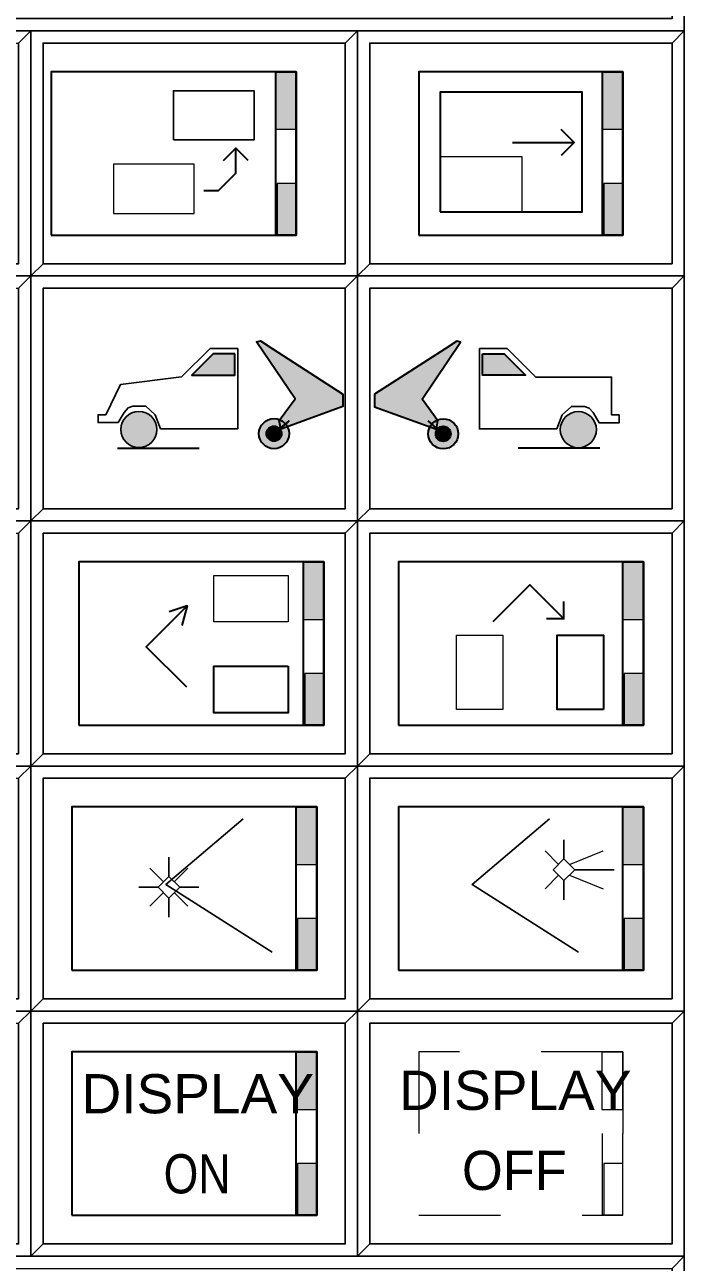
# Model space of a CAD drawing. Extents: x 95906.8 to 95923.6, y 90964.8 to 90972.8.
# Drawn here: x 95917.125 to 95917.932, y 90966.454 to 90967.969 of the extents above; entities that cross this region are included whole.
import ezdxf
from ezdxf.enums import TextEntityAlignment as Align

# ---------------------------------------------------------------- set-up
doc = ezdxf.new("R2010")
doc.units = 0
doc.header["$LTSCALE"] = 0.019
doc.linetypes.add('MEDIUM_DASHED', pattern=[4.5, 3, -1.5])
for name, color, linetype, lineweight in [('11', 7, 'Continuous', 25), ('2', 7, 'Continuous', 13), ('3', 7, 'Continuous', 25), ('6', 7, 'Continuous', 25)]:
    doc.layers.add(name, color=color, linetype=linetype, lineweight=lineweight)

msp = doc.modelspace()

# ---------------------------------------------------------------- hatches: boundary and pattern name
at = {"layer": '6'}
for points in [[(95917.4573, 90967.9117), (95917.4315, 90967.9117), (95917.4315, 90967.8412), (95917.4573, 90967.8412)], [(95917.8573, 90967.9117), (95917.8315, 90967.9117), (95917.8315, 90967.8412), (95917.8573, 90967.8412)], [(95917.4339, 90967.7117), (95917.4573, 90967.7117), (95917.4573, 90967.775), (95917.4339, 90967.775)], [(95917.8339, 90967.7117), (95917.8573, 90967.7117), (95917.8573, 90967.775), (95917.8339, 90967.775)], [(95917.4486, 90967.4845), (95917.4382, 90967.4746), (95917.4365, 90967.4846), (95917.456, 90967.5112), (95917.4087, 90967.5809), (95917.4134, 90967.5821), (95917.4276, 90967.5727), (95917.5143, 90967.5171), (95917.5143, 90967.5017), (95917.4394, 90967.4745), (95917.4382, 90967.4757)], [(95917.6186, 90967.4843), (95917.629, 90967.4744), (95917.6307, 90967.4844), (95917.6112, 90967.511), (95917.6585, 90967.5807), (95917.6538, 90967.5819), (95917.6396, 90967.5725), (95917.5529, 90967.5169), (95917.5529, 90967.5015), (95917.6278, 90967.4743), (95917.629, 90967.4755)], [(95917.3819, 90967.5664), (95917.3554, 90967.5664), (95917.3294, 90967.5404), (95917.3819, 90967.5404)], [(95917.6853, 90967.5662), (95917.7118, 90967.5662), (95917.7378, 90967.5402), (95917.6853, 90967.5402)], [(95917.2426, 90967.4737, 1), (95917.2867, 90967.4737, 1)], [(95917.8246, 90967.4735, 1), (95917.7805, 90967.4735, 1)], [(95917.4484, 90967.4686, 1), (95917.4116, 90967.4686, 1)], [(95917.6188, 90967.4684, 1), (95917.6556, 90967.4684, 1)], [(95917.4392, 90967.4686, 1), (95917.4208, 90967.4686, 1)], [(95917.628, 90967.4684, 1), (95917.6464, 90967.4684, 1)], [(95917.4912, 90967.3117), (95917.4654, 90967.3117), (95917.4654, 90967.2412), (95917.4912, 90967.2412)], [(95917.8823, 90967.3117), (95917.8565, 90967.3117), (95917.8565, 90967.2412), (95917.8823, 90967.2412)], [(95917.4678, 90967.1117), (95917.4912, 90967.1117), (95917.4912, 90967.175), (95917.4678, 90967.175)], [(95917.8589, 90967.1117), (95917.8823, 90967.1117), (95917.8823, 90967.175), (95917.8589, 90967.175)], [(95917.4823, 90967.0117), (95917.4565, 90967.0117), (95917.4565, 90966.9412), (95917.4823, 90966.9412)], [(95917.8823, 90967.0117), (95917.8565, 90967.0117), (95917.8565, 90966.9412), (95917.8823, 90966.9412)], [(95917.4589, 90966.8117), (95917.4823, 90966.8117), (95917.4823, 90966.875), (95917.4589, 90966.875)], [(95917.8589, 90966.8117), (95917.8823, 90966.8117), (95917.8823, 90966.875), (95917.8589, 90966.875)], [(95917.4823, 90966.7117), (95917.4565, 90966.7117), (95917.4565, 90966.6412), (95917.4823, 90966.6412)], [(95917.4589, 90966.5117), (95917.4823, 90966.5117), (95917.4823, 90966.575), (95917.4589, 90966.575)]]:
    msp.add_hatch(color=256, dxfattribs=at).paths.add_polyline_path(points)

# ---------------------------------------------------------------- linework, layer by layer
at = {"layer": '11'}
for points in [[(95917.1473, 90967.6767), (95917.5173, 90967.6767), (95917.5173, 90967.9467), (95917.1473, 90967.9467)], [(95917.5473, 90967.6767), (95917.9173, 90967.6767), (95917.9173, 90967.9467), (95917.5473, 90967.9467)], [(95917.1473, 90967.3767), (95917.5173, 90967.3767), (95917.5173, 90967.6467), (95917.1473, 90967.6467)], [(95917.5473, 90967.3767), (95917.9173, 90967.3767), (95917.9173, 90967.6467), (95917.5473, 90967.6467)], [(95917.1473, 90967.0767), (95917.5173, 90967.0767), (95917.5173, 90967.3467), (95917.1473, 90967.3467)], [(95917.5473, 90967.0767), (95917.9173, 90967.0767), (95917.9173, 90967.3467), (95917.5473, 90967.3467)], [(95917.1473, 90966.7767), (95917.5173, 90966.7767), (95917.5173, 90967.0467), (95917.1473, 90967.0467)], [(95917.5473, 90966.7767), (95917.9173, 90966.7767), (95917.9173, 90967.0467), (95917.5473, 90967.0467)], [(95917.1473, 90966.4767), (95917.5173, 90966.4767), (95917.5173, 90966.7467), (95917.1473, 90966.7467)], [(95917.5473, 90966.4767), (95917.9173, 90966.4767), (95917.9173, 90966.7467), (95917.5473, 90966.7467)]]:
    msp.add_lwpolyline(points, close=True, dxfattribs=at)
at = {"layer": '2'}
for points in [[(95916.7323, 90967.9617), (95916.7323, 90967.6617), (95916.7473, 90967.6767), (95916.7473, 90967.9467), (95917.1173, 90967.9467), (95917.1323, 90967.9617)], [(95917.1323, 90967.9617), (95917.1323, 90967.6617), (95917.1473, 90967.6767), (95917.1473, 90967.9467), (95917.5173, 90967.9467), (95917.5323, 90967.9617)], [(95917.5323, 90967.9617), (95917.5323, 90967.6617), (95917.5473, 90967.6767), (95917.5473, 90967.9467), (95917.9173, 90967.9467), (95917.9323, 90967.9617)], [(95916.7323, 90967.6617), (95916.7323, 90967.3617), (95916.7473, 90967.3767), (95916.7473, 90967.6467), (95917.1173, 90967.6467), (95917.1323, 90967.6617)], [(95917.1323, 90967.6617), (95917.1323, 90967.3617), (95917.1473, 90967.3767), (95917.1473, 90967.6467), (95917.5173, 90967.6467), (95917.5323, 90967.6617)], [(95917.5323, 90967.6617), (95917.5323, 90967.3617), (95917.5473, 90967.3767), (95917.5473, 90967.6467), (95917.9173, 90967.6467), (95917.9323, 90967.6617)], [(95916.7323, 90967.3617), (95916.7323, 90967.0617), (95916.7473, 90967.0767), (95916.7473, 90967.3467), (95917.1173, 90967.3467), (95917.1323, 90967.3617)], [(95917.1323, 90967.3617), (95917.1323, 90967.0617), (95917.1473, 90967.0767), (95917.1473, 90967.3467), (95917.5173, 90967.3467), (95917.5323, 90967.3617)], [(95917.5323, 90967.3617), (95917.5323, 90967.0617), (95917.5473, 90967.0767), (95917.5473, 90967.3467), (95917.9173, 90967.3467), (95917.9323, 90967.3617)], [(95916.7323, 90967.0617), (95916.7323, 90966.7617), (95916.7473, 90966.7767), (95916.7473, 90967.0467), (95917.1173, 90967.0467), (95917.1323, 90967.0617)], [(95917.1323, 90967.0617), (95917.1323, 90966.7617), (95917.1473, 90966.7767), (95917.1473, 90967.0467), (95917.5173, 90967.0467), (95917.5323, 90967.0617)], [(95917.5323, 90967.0617), (95917.5323, 90966.7617), (95917.5473, 90966.7767), (95917.5473, 90967.0467), (95917.9173, 90967.0467), (95917.9323, 90967.0617)], [(95916.7323, 90966.7617), (95916.7323, 90966.4617), (95916.7473, 90966.4767), (95916.7473, 90966.7467), (95917.1173, 90966.7467), (95917.1323, 90966.7617)], [(95917.1323, 90966.7617), (95917.1323, 90966.4617), (95917.1473, 90966.4767), (95917.1473, 90966.7467), (95917.5173, 90966.7467), (95917.5323, 90966.7617)], [(95917.5323, 90966.7617), (95917.5323, 90966.4617), (95917.5473, 90966.4767), (95917.5473, 90966.7467), (95917.9173, 90966.7467), (95917.9323, 90966.7617)], [(95916.3323, 90966.4617), (95916.3323, 90966.3617), (95916.3473, 90966.3767), (95916.3473, 90966.4467), (95917.9173, 90966.4467), (95917.9323, 90966.4617)]]:
    msp.add_lwpolyline(points, close=True, dxfattribs=at)
at = {"layer": '3'}
for points in [[(95916.3323, 90967.9617), (95917.9323, 90967.9617), (95917.9323, 90968.0617), (95917.9173, 90968.0467), (95917.9173, 90967.9767), (95916.3473, 90967.9767)], [(95916.7323, 90967.6617), (95917.1323, 90967.6617), (95917.1323, 90967.9617), (95917.1173, 90967.9467), (95917.1173, 90967.6767), (95916.7473, 90967.6767)], [(95917.1323, 90967.6617), (95917.5323, 90967.6617), (95917.5323, 90967.9617), (95917.5173, 90967.9467), (95917.5173, 90967.6767), (95917.1473, 90967.6767)], [(95917.5323, 90967.6617), (95917.9323, 90967.6617), (95917.9323, 90967.9617), (95917.9173, 90967.9467), (95917.9173, 90967.6767), (95917.5473, 90967.6767)], [(95916.7323, 90967.3617), (95917.1323, 90967.3617), (95917.1323, 90967.6617), (95917.1173, 90967.6467), (95917.1173, 90967.3767), (95916.7473, 90967.3767)], [(95917.1323, 90967.3617), (95917.5323, 90967.3617), (95917.5323, 90967.6617), (95917.5173, 90967.6467), (95917.5173, 90967.3767), (95917.1473, 90967.3767)], [(95917.5323, 90967.3617), (95917.9323, 90967.3617), (95917.9323, 90967.6617), (95917.9173, 90967.6467), (95917.9173, 90967.3767), (95917.5473, 90967.3767)], [(95916.7323, 90967.0617), (95917.1323, 90967.0617), (95917.1323, 90967.3617), (95917.1173, 90967.3467), (95917.1173, 90967.0767), (95916.7473, 90967.0767)], [(95917.1323, 90967.0617), (95917.5323, 90967.0617), (95917.5323, 90967.3617), (95917.5173, 90967.3467), (95917.5173, 90967.0767), (95917.1473, 90967.0767)], [(95917.5323, 90967.0617), (95917.9323, 90967.0617), (95917.9323, 90967.3617), (95917.9173, 90967.3467), (95917.9173, 90967.0767), (95917.5473, 90967.0767)], [(95916.7323, 90966.7617), (95917.1323, 90966.7617), (95917.1323, 90967.0617), (95917.1173, 90967.0467), (95917.1173, 90966.7767), (95916.7473, 90966.7767)], [(95917.1323, 90966.7617), (95917.5323, 90966.7617), (95917.5323, 90967.0617), (95917.5173, 90967.0467), (95917.5173, 90966.7767), (95917.1473, 90966.7767)], [(95917.5323, 90966.7617), (95917.9323, 90966.7617), (95917.9323, 90967.0617), (95917.9173, 90967.0467), (95917.9173, 90966.7767), (95917.5473, 90966.7767)], [(95916.7323, 90966.4617), (95917.1323, 90966.4617), (95917.1323, 90966.7617), (95917.1173, 90966.7467), (95917.1173, 90966.4767), (95916.7473, 90966.4767)], [(95917.1323, 90966.4617), (95917.5323, 90966.4617), (95917.5323, 90966.7617), (95917.5173, 90966.7467), (95917.5173, 90966.4767), (95917.1473, 90966.4767)], [(95917.5323, 90966.4617), (95917.9323, 90966.4617), (95917.9323, 90966.7617), (95917.9173, 90966.7467), (95917.9173, 90966.4767), (95917.5473, 90966.4767)], [(95916.3323, 90966.3617), (95917.9323, 90966.3617), (95917.9323, 90966.4617), (95917.9173, 90966.4467), (95917.9173, 90966.3767), (95916.3473, 90966.3767)]]:
    msp.add_lwpolyline(points, close=True, dxfattribs=at)
at = {"layer": '6', "lineweight": 35}
for p, q in [((95917.7977, 90967.8252), (95917.7817, 90967.8411)), ((95917.3832, 90967.8181), (95917.3678, 90967.8027)), ((95917.3237, 90967.258), (95917.3018, 90967.2503)), ((95917.7847, 90967.242), (95917.7635, 90967.242))]:
    msp.add_line(p, q, dxfattribs=at)
at = {"layer": '6', "linetype": 'MEDIUM_DASHED', "lineweight": 35}
for p, q in [((95917.2382, 90967.451), (95917.3876, 90967.451)), ((95917.829, 90967.4508), (95917.6796, 90967.4508))]:
    msp.add_line(p, q, dxfattribs=at)
at = {"layer": '6'}
for p, q in [((95917.785, 90966.9479), (95917.785, 90966.9713)), ((95917.785, 90966.9479), (95917.785, 90966.9713)), ((95917.3013, 90966.9266), (95917.3013, 90966.95)), ((95917.3013, 90966.9266), (95917.3013, 90966.95)), ((95917.7982, 90966.9346), (95917.8466, 90966.9346)), ((95917.7982, 90966.9346), (95917.8466, 90966.9346)), ((95917.785, 90966.9214), (95917.785, 90966.898)), ((95917.785, 90966.9214), (95917.785, 90966.898)), ((95917.2881, 90966.9133), (95917.2646, 90966.9133)), ((95917.3145, 90966.9133), (95917.3379, 90966.9133)), ((95917.3145, 90966.9133), (95917.3379, 90966.9133)), ((95917.3013, 90966.9001), (95917.3013, 90966.8767)), ((95917.3013, 90966.9001), (95917.3013, 90966.8767)), ((95917.5173, 90966.7147), (95917.5173, 90966.503)), ((95917.5173, 90966.7147), (95917.5173, 90966.503)), ((95917.5173, 90966.7147), (95917.5173, 90966.503)), ((95917.9173, 90966.7147), (95917.9173, 90966.503))]:
    msp.add_line(p, q, dxfattribs=at)
at = {"layer": '6', "linetype": 'MEDIUM_DASHED', "lineweight": 13}
for p, q in [((95917.7784, 90966.9412), (95917.7618, 90966.9578)), ((95917.7784, 90966.9412), (95917.7618, 90966.9578)), ((95917.7916, 90966.9412), (95917.8332, 90966.9578)), ((95917.7916, 90966.9412), (95917.8332, 90966.9578)), ((95917.2947, 90966.9199), (95917.2781, 90966.9365)), ((95917.2947, 90966.9199), (95917.2781, 90966.9365)), ((95917.3079, 90966.9199), (95917.3245, 90966.9365)), ((95917.3079, 90966.9199), (95917.3245, 90966.9365)), ((95917.7784, 90966.928), (95917.7618, 90966.9115)), ((95917.7784, 90966.928), (95917.7618, 90966.9115)), ((95917.7916, 90966.928), (95917.8332, 90966.9115)), ((95917.7916, 90966.928), (95917.8332, 90966.9115)), ((95917.2947, 90966.9067), (95917.2781, 90966.8902)), ((95917.2947, 90966.9067), (95917.2781, 90966.8902)), ((95917.3079, 90966.9067), (95917.3245, 90966.8902)), ((95917.3079, 90966.9067), (95917.3245, 90966.8902))]:
    msp.add_line(p, q, dxfattribs=at)
at = {"layer": '6', "lineweight": 13}
for p, q in [((95917.5173, 90966.503), (95917.5173, 90966.7147)), ((95917.5173, 90966.503), (95917.5173, 90966.7147)), ((95917.5173, 90966.503), (95917.5173, 90966.7147)), ((95917.9173, 90966.503), (95917.9173, 90966.7147))]:
    msp.add_line(p, q, dxfattribs=at)
at = {"layer": '6', "lineweight": 35}
for points in [[(95917.1573, 90967.7117), (95917.4573, 90967.7117), (95917.4573, 90967.9117), (95917.1573, 90967.9117)], [(95917.4573, 90967.7117), (95917.4323, 90967.7117), (95917.4323, 90967.9117), (95917.4573, 90967.9117)], [(95917.6073, 90967.7117), (95917.8573, 90967.7117), (95917.8573, 90967.9117), (95917.6073, 90967.9117)], [(95917.8573, 90967.7117), (95917.8323, 90967.7117), (95917.8323, 90967.9117), (95917.8573, 90967.9117)], [(95917.6334, 90967.7401), (95917.8072, 90967.7401), (95917.8072, 90967.8867), (95917.6334, 90967.8867)], [(95917.4486, 90967.4845), (95917.4382, 90967.4746), (95917.4365, 90967.4846), (95917.456, 90967.5112), (95917.4087, 90967.5809), (95917.4134, 90967.5821), (95917.4276, 90967.5727), (95917.5143, 90967.5171), (95917.5143, 90967.5017), (95917.4394, 90967.4745), (95917.4382, 90967.4757)], [(95917.6186, 90967.4843), (95917.629, 90967.4744), (95917.6307, 90967.4844), (95917.6112, 90967.511), (95917.6585, 90967.5807), (95917.6538, 90967.5819), (95917.6396, 90967.5725), (95917.5529, 90967.5169), (95917.5529, 90967.5015), (95917.6278, 90967.4743), (95917.629, 90967.4755)], [(95917.3819, 90967.5664), (95917.3554, 90967.5664), (95917.3294, 90967.5404), (95917.3819, 90967.5404)], [(95917.6853, 90967.5662), (95917.7118, 90967.5662), (95917.7378, 90967.5402), (95917.6853, 90967.5402)], [(95917.1912, 90967.1117), (95917.4912, 90967.1117), (95917.4912, 90967.3117), (95917.1912, 90967.3117)], [(95917.4912, 90967.1117), (95917.4662, 90967.1117), (95917.4662, 90967.3117), (95917.4912, 90967.3117)], [(95917.5823, 90967.1117), (95917.8823, 90967.1117), (95917.8823, 90967.3117), (95917.5823, 90967.3117)], [(95917.8823, 90967.1117), (95917.8573, 90967.1117), (95917.8573, 90967.3117), (95917.8823, 90967.3117)], [(95917.8333, 90967.1309), (95917.7765, 90967.1309), (95917.7765, 90967.2219), (95917.8333, 90967.2219)], [(95917.4472, 90967.1838), (95917.4472, 90967.127), (95917.3562, 90967.127), (95917.3562, 90967.1838)], [(95917.1823, 90966.8117), (95917.4823, 90966.8117), (95917.4823, 90967.0117), (95917.1823, 90967.0117)], [(95917.4823, 90966.8117), (95917.4573, 90966.8117), (95917.4573, 90967.0117), (95917.4823, 90967.0117)], [(95917.5823, 90966.8117), (95917.8823, 90966.8117), (95917.8823, 90967.0117), (95917.5823, 90967.0117)], [(95917.8823, 90966.8117), (95917.8573, 90966.8117), (95917.8573, 90967.0117), (95917.8823, 90967.0117)], [(95917.1823, 90966.5117), (95917.4823, 90966.5117), (95917.4823, 90966.7117), (95917.1823, 90966.7117)], [(95917.4823, 90966.5117), (95917.4573, 90966.5117), (95917.4573, 90966.7117), (95917.4823, 90966.7117)]]:
    msp.add_lwpolyline(points, close=True, dxfattribs=at)
at = {"layer": '6', "lineweight": 13}
for points in [[(95917.4573, 90967.9117), (95917.4315, 90967.9117), (95917.4315, 90967.8412), (95917.4573, 90967.8412)], [(95917.8573, 90967.9117), (95917.8315, 90967.9117), (95917.8315, 90967.8412), (95917.8573, 90967.8412)], [(95917.4339, 90967.7117), (95917.4573, 90967.7117), (95917.4573, 90967.775), (95917.4339, 90967.775)], [(95917.8339, 90967.7117), (95917.8573, 90967.7117), (95917.8573, 90967.775), (95917.8339, 90967.775)], [(95917.4912, 90967.3117), (95917.4654, 90967.3117), (95917.4654, 90967.2412), (95917.4912, 90967.2412)], [(95917.8823, 90967.3117), (95917.8565, 90967.3117), (95917.8565, 90967.2412), (95917.8823, 90967.2412)], [(95917.4678, 90967.1117), (95917.4912, 90967.1117), (95917.4912, 90967.175), (95917.4678, 90967.175)], [(95917.8589, 90967.1117), (95917.8823, 90967.1117), (95917.8823, 90967.175), (95917.8589, 90967.175)], [(95917.4823, 90967.0117), (95917.4565, 90967.0117), (95917.4565, 90966.9412), (95917.4823, 90966.9412)], [(95917.8823, 90967.0117), (95917.8565, 90967.0117), (95917.8565, 90966.9412), (95917.8823, 90966.9412)], [(95917.785, 90966.9214), (95917.7983, 90966.9347), (95917.785, 90966.9479), (95917.7717, 90966.9347)], [(95917.785, 90966.9214), (95917.7983, 90966.9347), (95917.785, 90966.9479), (95917.7717, 90966.9347)], [(95917.3013, 90966.9001), (95917.3146, 90966.9134), (95917.3013, 90966.9266), (95917.288, 90966.9134)], [(95917.3013, 90966.9001), (95917.3146, 90966.9134), (95917.3013, 90966.9266), (95917.288, 90966.9134)], [(95917.4589, 90966.8117), (95917.4823, 90966.8117), (95917.4823, 90966.875), (95917.4589, 90966.875)], [(95917.8589, 90966.8117), (95917.8823, 90966.8117), (95917.8823, 90966.875), (95917.8589, 90966.875)], [(95917.4823, 90966.7117), (95917.4565, 90966.7117), (95917.4565, 90966.6412), (95917.4823, 90966.6412)], [(95917.4589, 90966.5117), (95917.4823, 90966.5117), (95917.4823, 90966.575), (95917.4589, 90966.575)]]:
    msp.add_lwpolyline(points, close=True, dxfattribs=at)
at = {"layer": '6'}
for points in [[(95917.3068, 90967.8282), (95917.4055, 90967.8282), (95917.4055, 90967.8885), (95917.3068, 90967.8885)], [(95917.3857, 90967.573), (95917.3517, 90967.573), (95917.3166, 90967.538), (95917.242, 90967.5287), (95917.2239, 90967.4917), (95917.2145, 90967.4917), (95917.2145, 90967.4822), (95917.2391, 90967.4822), (95917.2466, 90967.4945), (95917.2514, 90967.5002), (95917.257, 90967.5021), (95917.2731, 90967.5021), (95917.2845, 90967.4917), (95917.2911, 90967.4746), (95917.3857, 90967.4746)], [(95917.6815, 90967.5728), (95917.7155, 90967.5728), (95917.7506, 90967.5378), (95917.8433, 90967.5379), (95917.8433, 90967.4915), (95917.8527, 90967.4915), (95917.8527, 90967.482), (95917.8281, 90967.482), (95917.8206, 90967.4943), (95917.8158, 90967.5), (95917.8102, 90967.5019), (95917.7941, 90967.5019), (95917.7827, 90967.4915), (95917.7761, 90967.4744), (95917.6815, 90967.4744)]]:
    msp.add_lwpolyline(points, close=True, dxfattribs=at)
at = {"layer": '6', "lineweight": 35}
for points in [[(95917.3442, 90967.7661), (95917.3619, 90967.7661), (95917.3832, 90967.7874), (95917.3832, 90967.8181), (95917.398, 90967.8033)], [(95917.7221, 90967.8252), (95917.7977, 90967.8252), (95917.7817, 90967.8092)], [(95917.6985, 90967.2385), (95917.7434, 90967.2834), (95917.7847, 90967.242), (95917.7847, 90967.2633)], [(95917.3231, 90967.1581), (95917.2734, 90967.2077), (95917.3237, 90967.258), (95917.3172, 90967.2338)]]:
    msp.add_lwpolyline(points, dxfattribs=at)
at = {"layer": '6', "linetype": 'MEDIUM_DASHED', "lineweight": 13}
for points in [[(95917.2335, 90967.7383), (95917.3322, 90967.7383), (95917.3322, 90967.7986), (95917.2335, 90967.7986)], [(95917.6334, 90967.7401), (95917.7339, 90967.7401), (95917.7339, 90967.8075), (95917.6334, 90967.8075)], [(95917.4472, 90967.2949), (95917.4472, 90967.2381), (95917.3562, 90967.2381), (95917.3562, 90967.2949)], [(95917.7103, 90967.1309), (95917.6535, 90967.1309), (95917.6535, 90967.2219), (95917.7103, 90967.2219)], [(95917.6073, 90966.5117), (95917.8573, 90966.5117), (95917.8573, 90966.7117), (95917.6073, 90966.7117)], [(95917.8573, 90966.7117), (95917.8315, 90966.7117), (95917.8315, 90966.6412), (95917.8573, 90966.6412)], [(95917.8573, 90966.5117), (95917.8323, 90966.5117), (95917.8323, 90966.7117), (95917.8573, 90966.7117)], [(95917.8339, 90966.5117), (95917.8573, 90966.5117), (95917.8573, 90966.575), (95917.8339, 90966.575)]]:
    msp.add_lwpolyline(points, close=True, dxfattribs=at)
at = {"layer": '6'}
for points in [[(95917.3922, 90966.9969), (95917.2976, 90966.9165), (95917.4277, 90966.8337)], [(95917.7672, 90966.9969), (95917.6726, 90966.9165), (95917.8027, 90966.8337)]]:
    msp.add_lwpolyline(points, dxfattribs=at)
for centre in [(95917.2646, 90967.4737), (95917.8026, 90967.4735)]:
    msp.add_circle(centre, 0.0221, dxfattribs=at)
at = {"layer": '6', "lineweight": 35}
for centre, radius in [((95917.43, 90967.4686), 0.0184), ((95917.6372, 90967.4684), 0.0184), ((95917.43, 90967.4686), 0.00923), ((95917.6372, 90967.4684), 0.00923)]:
    msp.add_circle(centre, radius, dxfattribs=at)

# ---------------------------------------------------------------- texts
at = {"layer": '6'}
for s, width, p in [('DISPLAY', 1.05, (95917.3366, 90966.6365)), ('DISPLAY', 1.05, (95917.7254, 90966.6407)), ('ON', 0.85, (95917.3358, 90966.5385))]:
    msp.add_text(s, height=0.048, dxfattribs=dict(at, width=width)).set_placement(p, align=Align.CENTER)
msp.add_text('OFF', height=0.048, dxfattribs=at).set_placement((95917.7243, 90966.5427), align=Align.CENTER)

doc.saveas('drawing.dxf')
